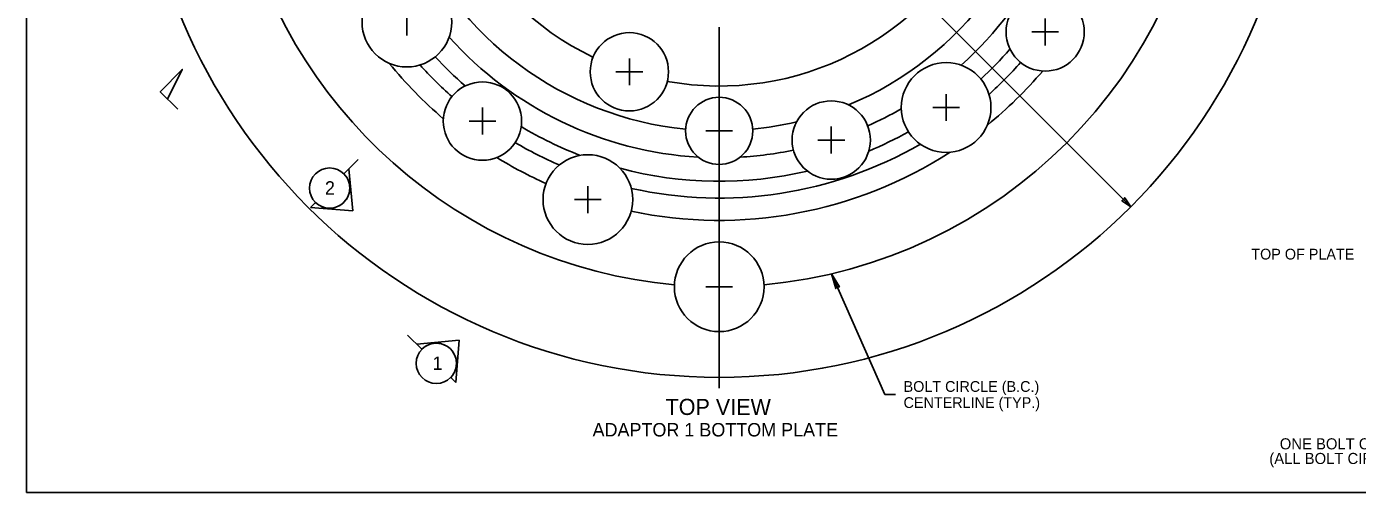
# Model space of a CAD drawing. Extents: x 99862 to 103151, y 100000 to 114076.
# Drawn here: x 99862 to 101844, y 103000 to 103693 of the extents above; entities that cross this region are included whole.
import ezdxf

# ---------------------------------------------------------------- set-up
doc = ezdxf.new("R2010")
doc.units = 0
for name, color, linetype in [('Level 1', 7, 'Continuous'), ('Level 14', 7, 'Continuous'), ('Level 15', 7, 'Continuous'), ('Level 20', 7, 'Continuous'), ('Level 60', 7, 'Continuous')]:
    doc.layers.add(name, color=color, linetype=linetype)

msp = doc.modelspace()

# ---------------------------------------------------------------- linework, layer by layer
at = {"layer": 'Level 1'}
msp.add_lwpolyline([(99862, 102999.5), (103151, 102999.5), (103151, 105075.5), (99862, 105075.5)], close=True, dxfattribs=at)
at = {"layer": 'Level 14'}
msp.add_line((100893.5, 103691.7), (100893.5, 103154.7), dxfattribs=at)
for radius, start, end in [(433.2, 169.7193, 244.2807), (540, 311.8529, 356.6916), (500, 292.6811, 354.268), (732, 275.2304, 354.7696), (732, 192.0911, 264.7696), (500, 202.6811, 264.268), (433.2, 259.7193, 334.2807), (540, 221.8529, 266.6916), (575, 312.66, 318.8585), (633.2, 219.1137, 229.5419), (575, 222.66, 228.8585), (600, 312.0454, 318.4287), (600, 222.0454, 228.4287), (633.2, 309.1137, 319.5419), (540, 294.191, 300.1471), (575, 239.1415, 248.8863), (500, 275.732, 283.3189), (600, 239.5713, 246.6098), (575, 292.7981, 299.34), (633.2, 258.0473, 302.8863), (600, 257.3902, 299.9546), (540, 273.3084, 281.809), (633.2, 238.4581, 245.9527), (575, 255.1137, 283.2019)]:
    msp.add_arc((100893.5, 104037.5), radius, start, end, dxfattribs=at)
at = {"layer": 'Level 15'}
for p, q in [((101506.5, 103424.6), (100280.6, 104650.4)), ((101140.1, 103145.1), (101060.7, 103324.9)), ((101156.1, 103145.1), (101140.1, 103145.1))]:
    msp.add_line(p, q, dxfattribs=at)
for points in [[(101506.5, 103424.6), (101497.5, 103437.9), (101495.9, 103435.2), (101493.2, 103433.5)], [(101060.7, 103324.9), (101067.1, 103302.8), (101069.4, 103304.9), (101072.6, 103305.2)]]:
    msp.add_lwpolyline(points, close=True, dxfattribs=at)
at = {"layer": 'Level 20'}
for p, q in [((100428.4, 103719.5), (100428.4, 103679.5)), ((101379, 103704.8), (101379, 103664.8)), ((101399, 103684.8), (101359, 103684.8)), ((100759.7, 103645.5), (100759.7, 103605.5)), ((100779.7, 103625.5), (100739.7, 103625.5)), ((100087, 103570), (100061, 103595.6)), ((101231.5, 103592.3), (101231.5, 103552.3)), ((100540.9, 103572.1), (100540.9, 103532.1)), ((101251.5, 103572.3), (101211.5, 103572.3)), ((100560.9, 103552.1), (100520.9, 103552.1)), ((100893.5, 103557.5), (100893.5, 103517.5)), ((101060.4, 103543.9), (101060.4, 103503.9)), ((100913.5, 103537.5), (100873.5, 103537.5)), ((101080.4, 103523.9), (101040.4, 103523.9)), ((100334.4, 103473.7), (100355.6, 103495)), ((100341.9, 103481.3), (100334.4, 103473.7)), ((100347.7, 103418.3), (100341.9, 103481.3)), ((100697.9, 103455.3), (100697.9, 103415.3)), ((100292.2, 103431.1), (100284.7, 103423.6)), ((100284.7, 103423.6), (100347.7, 103418.3)), ((100717.9, 103435.3), (100677.9, 103435.3)), ((100893.5, 103325.5), (100893.5, 103285.5)), ((100913.5, 103305.5), (100873.5, 103305.5)), ((100450.8, 103212.5), (100429.4, 103233.6)), ((100506.2, 103226.1), (100443.2, 103220)), ((100501.2, 103163), (100506.2, 103226.1)), ((100443.2, 103220), (100450.8, 103212.5)), ((100493.6, 103170.5), (100501.2, 103163))]:
    msp.add_line(p, q, dxfattribs=at)
msp.add_lwpolyline([(100072, 103584.7), (100093.8, 103629), (100061, 103595.6)], close=True, dxfattribs=at)
for centre, radius in [((100893.5, 104037.5), 866.8), ((100428.4, 103699.5), 66.8), ((101379, 103684.8), 58.3), ((100759.7, 103625.5), 58.3), ((101231.5, 103572.3), 66.8), ((100540.9, 103552.1), 58.3), ((100893.5, 103537.5), 50), ((101060.4, 103523.9), 58.3), ((100697.9, 103435.3), 66.8), ((100313.3, 103452.4), 30), ((100893.5, 103305.5), 66.8), ((100472.2, 103191.5), 30)]:
    msp.add_circle(centre, radius, dxfattribs=at)
for centre, start, end in [((100313.3, 103452.4), 225.2348, 45.2392), ((100472.2, 103191.5), 315.5026, 135.507)]:
    msp.add_arc(centre, 30, start, end, dxfattribs=at)
at = {"layer": 'Level 60'}
msp.add_line((99862, 102999.5), (99862, 102999.5), dxfattribs=at)

# ---------------------------------------------------------------- texts
at = {"layer": 'Level 20'}
for s, height, p in [('2', 20, (100306.3, 103442.6)), ('TOP OF PLATE', 16, (101686, 103346.1)), ('1', 20, (100466.5, 103181.7)), ('BOLT CIRCLE (B.C.)', 16, (101168.1, 103149.1)), ('TOP VIEW', 24, (100813.6, 103114.7)), ('CENTERLINE (TYP.)', 16, (101168.1, 103125.1)), ('ADAPTOR 1 BOTTOM PLATE', 20, (100704.9, 103082.7)), ('ONE BOLT CIRCLE CENTERLINE SHOWN', 16.5, (101728.4, 103063.5)), ('(ALL BOLT CIRCLE CENTERLINES SIMILAR)', 16.5, (101712.8, 103041.7))]:
    msp.add_text(s, height=height, dxfattribs=at).set_placement(p)

doc.saveas('drawing.dxf')
